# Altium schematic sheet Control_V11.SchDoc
size 302 x 215 mm
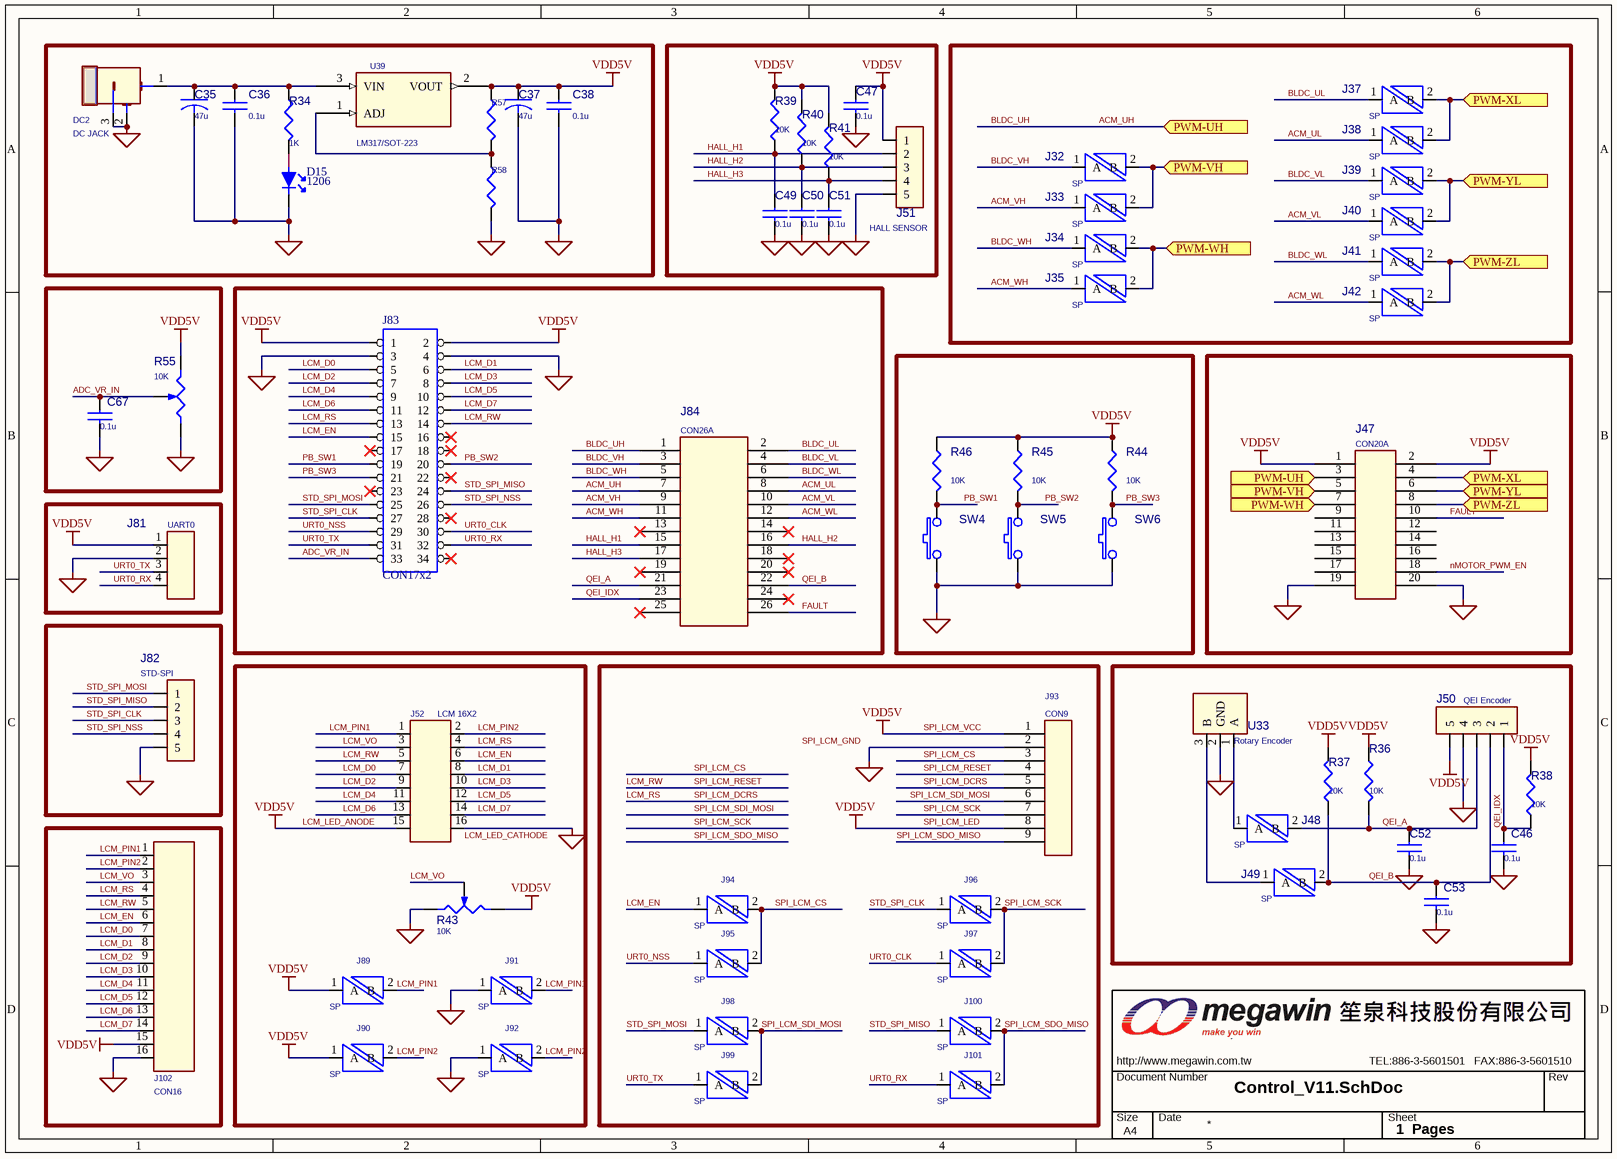
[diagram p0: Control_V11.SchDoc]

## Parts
C35  47u  [CEC063P025]
C36  0.1u  [0805C]
C37  47u  [CEC063P025]
C38  0.1u  [0805C]
C46  0.1u  [0805C]
C47  0.1u  [0805C]
C49  0.1u  [0805C]
C50  0.1u  [0805C]
C51  0.1u  [0805C]
C52  0.1u  [0805C]
C53  0.1u  [0805C]
C67  0.1u  [0805C]
D15  1206  [1206d]
DC2  DC JACK  [JACK_DC_0]
J32  SP  [JUMP2_SMD]
J33  SP  [JUMP2_SMD]
J34  SP  [JUMP2_SMD]
J35  SP  [JUMP2_SMD]
J37  SP  [JUMP2_SMD]
J38  SP  [JUMP2_SMD]
J39  SP  [JUMP2_SMD]
J40  SP  [JUMP2_SMD]
J41  SP  [JUMP2_SMD]
J42  SP  [JUMP2_SMD]
J47  CON20A  [PS10X2P254F_90]
J48  SP  [JUMP2_SMD]
J49  SP  [JUMP2_SMD]
J50  QEI Encoder  [PW5P3.5_90]
J51  HALL SENSOR  [PW5P3.5_90]
J52  LCM 16X2  [PCB_16LCD118X36]
J81  UART0  [PS4P254]
J82  STD-SPI  [PS5P254]
J83  CON17x2  [PS17X2P254]
J84  CON26A  [PS13X2P254]
J89  SP  [JUMP2_SMD]
J90  SP  [JUMP2_SMD]
J91  SP  [JUMP2_SMD]
J92  SP  [JUMP2_SMD]
J93  CON9  [PCB9_LCD_QVGA 2.2 TFT SPI]
J94  SP  [JUMP2_SMD]
J95  SP  [JUMP2_SMD]
J96  SP  [JUMP2_SMD]
J97  SP  [JUMP2_SMD]
J98  SP  [JUMP2_SMD]
J99  SP  [JUMP2_SMD]
J100  SP  [JUMP2_SMD]
J101  SP  [JUMP2_SMD]
J102  CON16  [LCD16P80X31.4]
MW1  OrgAddr3: TEL:886-3-5601501   FAX:886-3-5601510  Page Size: A4  [MEGAWIN_3.4]  (hidden comment: MW-A4)  (no BOM)
R34  1K  [0805R]
R36  10K  [0805R]
R37  10K  [0805R]
R38  10K  [0805R]
R39  10K  [0805R]
R40  10K  [0805R]
R41  10K  [0805R]
R43  10K  [vr3p]
R44  10K  [0805R]
R45  10K  [0805R]
R46  10K  [0805R]
R55  10K  [VR5P2.5]
R57  RESISTOR  [0805r]  (value not drawn)
R58  RESISTOR  [0805r]  (value not drawn)
SW4  START  [SW_T]  (value not drawn)
SW5  CW/CCW  [SW_T]  (value not drawn)
SW6  STOP  [SW_T]  (value not drawn)
U33  Rotary Encoder  [REC_3P]
U39  LM317/SOT-223  [sot223]

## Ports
PWM-UH (in), PWM-VH (in), PWM-WH (in), PWM-XL (in), PWM-YL (in), PWM-ZL (in)

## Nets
GND_S: C35.2 C36.2 C37.2 C38.2 C46.2 C47.2 C49.2 C50.2 C51.2 C52.2 C53.2 C67.2 D15.2 DC2.2(NA) DC2.3(DC-) J47.19 J47.20 J50.4 J51.5 J52.16 J81.2 J82.5 J83.3 J83.4 J91.1(A) J92.1(A) J93.2 J102.16 R43.1(A) R55.1(A) R58.2 SW4.1 SW5.1 SW6.1 U33.2(GND)
LCM_LED_ANODE: C37.1 C38.1 C47.1 J47.1 J47.2 J50.5 J51.1 J52.15 J81.1 J83.1 J83.2 J89.1(A) J90.1(A) J93.1 J93.8 J102.15 R36.1 R37.2 R38.2 R39.2 R40.2 R41.2 R43.3(B) R44.1 R45.1 R46.1 R55.3(B) R57.1 U39.2(VOUT)  [also labelled SPI_LCM_LED, SPI_LCM_VCC, VDD5V]
ACM_UH: J47.3 J84.1 J84.7 ; port PWM-UH  [also labelled BLDC_UH]
ACM_UL: J38.1(A) J84.8
ACM_VH: J33.1(A) J84.9
ACM_VL: J40.1(A) J84.10
ACM_WH: J35.1(A) J84.11
ACM_WL: J42.1(A) J84.12
ADC_VR_IN: C67.1 J83.33 R55.2(WIPER)
BLDC_UL: J37.1(A) J84.2
BLDC_VH: J32.1(A) J84.3
BLDC_VL: J39.1(A) J84.4
BLDC_WH: J34.1(A) J84.5
BLDC_WL: J41.1(A) J84.6
FAULT: J47.10 J84.26
HALL_H1: C49.1 J51.2 J84.15 R39.1
HALL_H2: C50.1 J51.3 J84.16 R40.1
HALL_H3: C51.1 J51.4 J84.17 R41.1
LCM_D0: J52.7 J83.5 J102.7
LCM_D1: J52.8 J83.6 J102.8
LCM_D2: J52.9 J83.7 J102.9
LCM_D3: J52.10 J83.8 J102.10
LCM_D4: J52.11 J83.9 J102.11
LCM_D5: J52.12 J83.10 J102.12
LCM_D6: J52.13 J83.11 J102.13
LCM_D7: J52.14 J83.12 J102.14
LCM_EN: J52.6 J83.15 J94.1(A) J102.6
LCM_PIN1: J52.1 J89.2(B) J91.2(B) J102.1
LCM_PIN2: J52.2 J90.2(B) J92.2(B) J102.2
LCM_RS: J52.4 J83.13 J93.5 J102.4  [also labelled SPI_LCM_DCRS]
LCM_RW: J52.5 J83.14 J93.4 J102.5  [also labelled SPI_LCM_RESET]
LCM_VO: J52.3 J102.3 R43.2(WIPER)
nMOTOR_PWM_EN: J47.18
PB_SW1: J83.19 R46.2 SW4.2
PB_SW2: J83.20 R45.2 SW5.2
PB_SW3: J83.21 R44.2 SW6.2
PWM-VH: J32.2(B) J33.2(B) J47.5 ; port PWM-VH
PWM-WH: J34.2(B) J35.2(B) J47.7 ; port PWM-WH
PWM-XL: J37.2(B) J38.2(B) J47.4 ; port PWM-XL
PWM-YL: J39.2(B) J40.2(B) J47.6 ; port PWM-YL
PWM-ZL: J41.2(B) J42.2(B) J47.8 ; port PWM-ZL
QEI_A: C52.1 J48.2(B) J50.3 J84.21 R36.2
QEI_B: C53.1 J49.2(B) J50.2 J84.22 R37.1
QEI_IDX: C46.1 J50.1 J84.23 R38.1
SPI_LCM_CS: J93.3 J94.2(B) J95.2(B)
SPI_LCM_SCK: J93.7 J96.2(B) J97.2(B)
SPI_LCM_SDI_MOSI: J93.6 J98.2(B) J99.2(B)
SPI_LCM_SDO_MISO: J93.9 J100.2(B) J101.2(B)
STD_SPI_CLK: J82.3 J83.27 J96.1(A)
STD_SPI_MISO: J82.2 J83.24 J100.1(A)
STD_SPI_MOSI: J82.1 J83.25 J98.1(A)
STD_SPI_NSS: J82.4 J83.26
URT0_CLK: J83.30 J97.1(A)
URT0_NSS: J83.29 J95.1(A)
URT0_RX: J81.4 J83.32 J101.1(A)
URT0_TX: J81.3 J83.31 J99.1(A)
NetC35_1: C35.1 C36.1 DC2.1(DC+) R34.1 U39.3(VIN)
NetD15_1: D15.1 R34.2
NetJ48_1: J48.1(A) U33.1(A)
NetJ49_1: J49.1(A) U33.3(B)
NetR57_2: R57.2 R58.1 U39.1(ADJ)

Not connected (* = marked no-connect by the designer): J47 9 11 12 13 14 15 16 17; J83 16* 17* 18* 22* 23* 28* 34*; J84 13* 14* 18* 19* 20* 24* 25*

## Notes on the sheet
- 1  Pages
- Labels drawn without touching a wire or pin: LCM_LED_CATHODE, SPI_LCM_GND

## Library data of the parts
C35 C37 = CAP
C36 C38 C46 C47 C49-C53 C67 = CAP NP
D15 = LED_sc
DC2 = JACK_DC2
J50 J51 J82 = CON5
J52 = CON16A
J81 = CON4
MW1 = MW_A4_1S
R34 R36-R41 R44-R46 = RESISTOR
R43 R55 = RESISTOR VAR
SW4-SW6 = SW PUSHBUTTON
U39 = LM317/TO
